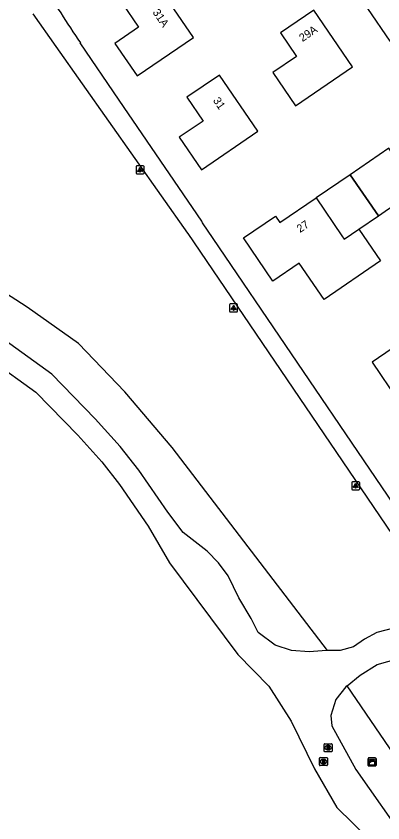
# Model space of a CAD drawing. Extents: x 155275 to 156263, y 382654 to 383635.
# Drawn here: x 155420.9 to 155466.7, y 383140.8 to 383241.6 of the extents above; entities that cross this region are included whole.
import ezdxf

# ---------------------------------------------------------------- set-up
doc = ezdxf.new("R2010")
doc.units = 0
for name, color, linetype in [('IMGEO_Groenvoorziening', 7, 'Continuous'), ('IMGEO_Kast', 7, 'Continuous'), ('IMGEO_Lichtpunt', 7, 'Continuous'), ('IMGEO_Pand', 7, 'Continuous'), ('IMGEO_Pand_nummerreeks', 7, 'Continuous'), ('IMGEO_Pand_overbouw', 7, 'Continuous'), ('IMGEO_Rioolput', 7, 'Continuous'), ('IMGEO_Voetpad_halfverhard', 7, 'Continuous'), ('IMGEO_Voetpad_open', 7, 'Continuous')]:
    doc.layers.add(name, color=color, linetype=linetype)

msp = doc.modelspace()

# ---------------------------------------------------------------- linework, layer by layer
at = {"layer": 'IMGEO_Groenvoorziening'}
for points in [[(155459.78, 383162.34), (155440.37, 383187.68), (155434.48, 383194.63), (155428.68, 383200.68), (155422.29, 383205.23), (155418.85, 383207.42), (155413.45, 383209.36), (155409.53, 383210.67), (155406.49, 383211.64), (155401.05, 383212.16), (155397.68, 383212.16), (155393.94, 383212.01), (155388.96, 383210.31), (155372.51, 383201.68)], [(155532.26, 383055.3), (155462.23, 383157.92)]]:
    msp.add_lwpolyline(points, dxfattribs=at)
at = {"layer": 'IMGEO_Kast'}
for p, q in [((155464.9, 383148.91), (155465.74, 383148.91)), ((155465.74, 383148.91), (155464.9, 383148.91)), ((155464.83, 383147.98), (155464.83, 383148.82)), ((155464.83, 383148.82), (155464.83, 383147.98)), ((155465.75, 383147.91), (155464.91, 383147.91)), ((155464.91, 383147.91), (155465.75, 383147.91)), ((155465.83, 383148.83), (155465.83, 383147.99)), ((155465.83, 383147.99), (155465.83, 383148.83))]:
    msp.add_line(p, q, dxfattribs=at)
for points in [[(155465.02, 383148.7), (155465.62, 383148.7), (155465.62, 383148.61), (155465.02, 383148.61), (155465.02, 383148.7)], [(155465.02, 383148.52), (155465.62, 383148.52), (155465.62, 383148.03), (155465.02, 383148.03), (155465.02, 383148.52)]]:
    msp.add_lwpolyline(points, dxfattribs=at)
msp.add_circle((155465.11, 383148.37), 0.0377, dxfattribs=at)
for centre, start, end in [((155464.91, 383148.83), 92.4484, 184.2845), ((155464.91, 383148.83), 92.4484, 184.2845), ((155465.75, 383148.83), 2.4484, 94.2845), ((155465.75, 383148.83), 2.4484, 94.2845), ((155464.91, 383147.99), 182.4484, 274.2845), ((155464.91, 383147.99), 182.4484, 274.2845), ((155465.75, 383147.99), 272.4484, 4.2845), ((155465.75, 383147.99), 272.4484, 4.2845)]:
    msp.add_arc(centre, 0.0779, start, end, dxfattribs=at)
at = {"layer": 'IMGEO_Lichtpunt'}
for p, q in [((155435.88, 383222.77), (155435.88, 383221.96)), ((155435.88, 383222.77), (155435.88, 383221.96)), ((155436.78, 383222.86), (155435.97, 383222.86)), ((155436.78, 383222.86), (155435.97, 383222.86)), ((155436.87, 383221.96), (155436.87, 383222.77)), ((155436.87, 383221.96), (155436.87, 383222.77)), ((155435.97, 383221.86), (155436.78, 383221.86)), ((155435.97, 383221.86), (155436.78, 383221.86)), ((155447.55, 383205.53), (155447.55, 383204.72)), ((155447.55, 383205.53), (155447.55, 383204.72)), ((155448.45, 383205.62), (155447.64, 383205.62)), ((155448.45, 383205.62), (155447.64, 383205.62)), ((155448.54, 383204.72), (155448.54, 383205.53)), ((155448.54, 383204.72), (155448.54, 383205.53)), ((155447.64, 383204.62), (155448.45, 383204.62)), ((155447.64, 383204.62), (155448.45, 383204.62)), ((155462.79, 383183.3), (155462.79, 383182.5)), ((155462.79, 383183.3), (155462.79, 383182.5)), ((155463.69, 383183.4), (155462.89, 383183.4)), ((155463.69, 383183.4), (155462.89, 383183.4)), ((155463.79, 383182.5), (155463.79, 383183.3)), ((155463.79, 383182.5), (155463.79, 383183.3)), ((155462.89, 383182.4), (155463.69, 383182.4)), ((155462.89, 383182.4), (155463.69, 383182.4))]:
    msp.add_line(p, q, dxfattribs=at)
for points in [[(155436.25, 383222.43), (155436.29, 383222.4), (155436.1, 383222.14), (155436.06, 383222.17), (155436.25, 383222.43)], [(155436.35, 383222.38), (155436.4, 383222.38), (155436.4, 383222.06), (155436.35, 383222.06), (155436.35, 383222.38)], [(155436.46, 383222.4), (155436.5, 383222.43), (155436.69, 383222.17), (155436.65, 383222.14), (155436.46, 383222.4)], [(155447.92, 383205.19), (155447.96, 383205.16), (155447.77, 383204.9), (155447.73, 383204.93), (155447.92, 383205.19)], [(155448.02, 383205.14), (155448.07, 383205.14), (155448.07, 383204.82), (155448.02, 383204.82), (155448.02, 383205.14)], [(155448.13, 383205.16), (155448.17, 383205.19), (155448.36, 383204.93), (155448.32, 383204.9), (155448.13, 383205.16)], [(155463.17, 383182.97), (155463.21, 383182.94), (155463.02, 383182.68), (155462.98, 383182.7), (155463.17, 383182.97)], [(155463.27, 383182.92), (155463.32, 383182.92), (155463.32, 383182.6), (155463.27, 383182.6), (155463.27, 383182.92)], [(155463.38, 383182.94), (155463.42, 383182.97), (155463.6, 383182.7), (155463.57, 383182.68), (155463.38, 383182.94)]]:
    msp.add_lwpolyline(points, dxfattribs=at)
for centre in [(155436.38, 383222.56), (155448.05, 383205.32), (155463.29, 383183.1)]:
    msp.add_circle(centre, 0.0994, dxfattribs=at)
for centre, start, end in [((155435.97, 383222.77), 90, 180), ((155435.97, 383222.77), 90, 180), ((155436.78, 383222.77), 0, 90), ((155436.78, 383222.77), 0, 90), ((155435.97, 383221.96), 180, 270), ((155435.97, 383221.96), 180, 270), ((155436.78, 383221.96), 270, 0), ((155436.78, 383221.96), 270, 360), ((155447.64, 383205.53), 90, 180), ((155447.64, 383205.53), 90, 180), ((155448.45, 383205.53), 0, 90), ((155448.45, 383205.53), 0, 90), ((155447.64, 383204.72), 180, 270), ((155447.64, 383204.72), 180, 270), ((155448.45, 383204.72), 270, 0), ((155448.45, 383204.72), 270, 360), ((155462.89, 383183.3), 90, 180), ((155462.89, 383183.3), 90, 180), ((155463.69, 383183.3), 0, 90), ((155463.69, 383183.3), 0, 90), ((155462.89, 383182.5), 180, 270), ((155462.89, 383182.5), 180, 270), ((155463.69, 383182.5), 270, 0), ((155463.69, 383182.5), 270, 360)]:
    msp.add_arc(centre, 0.0946, start, end, dxfattribs=at)
at = {"layer": 'IMGEO_Pand'}
for points in [[(155469.81, 383250.28), (155465.72, 383247.49), (155467.74, 383244.52), (155464.78, 383242.51), (155467.56, 383238.46), (155474.6, 383243.27), (155469.81, 383250.28)], [(155438.24, 383245.97), (155434.16, 383243.2), (155436.2, 383240.2), (155433.24, 383238.16), (155436.02, 383234.12), (155443.05, 383238.92), (155438.24, 383245.97)], [(155458.08, 383242.32), (155453.92, 383239.49), (155455.92, 383236.53), (155452.95, 383234.51), (155455.79, 383230.35), (155462.91, 383235.22), (155458.08, 383242.32)], [(155446.28, 383234.21), (155442.22, 383231.44), (155444.25, 383228.45), (155441.27, 383226.44), (155444.04, 383222.38), (155451.08, 383227.19), (155446.28, 383234.21)], [(155453.28, 383216.6), (155453.84, 383215.78), (155458.35, 383218.86), (155461.58, 383214.13), (155461.87, 383213.71), (155463.7, 383214.96), (155466.4, 383211.02), (155459.35, 383206.19), (155456.25, 383210.73), (155452.94, 383208.47), (155449.27, 383213.87), (155453.28, 383216.6)], [(155476.21, 383211.82), (155473.43, 383209.92), (155476.24, 383205.79), (155465.34, 383198.36), (155468.55, 383193.62), (155471.85, 383195.86)]]:
    msp.add_lwpolyline(points, dxfattribs=at)
at = {"layer": 'IMGEO_Pand_overbouw'}
for points in [[(155462.6, 383221.76), (155466.12, 383216.61), (155466.97, 383217.19), (155470.96, 383219.9), (155470.82, 383220.1), (155470.67, 383220.31), (155467.43, 383225.06)], [(155462.6, 383221.76), (155458.35, 383218.86), (155461.58, 383214.13), (155461.87, 383213.71), (155463.7, 383214.96), (155466.12, 383216.61)]]:
    msp.add_lwpolyline(points, close=True, dxfattribs=at)
at = {"layer": 'IMGEO_Rioolput'}
for p, q in [((155459.34, 383149.76), (155459.34, 383150.61)), ((155459.42, 383150.69), (155460.27, 383150.69)), ((155459.83, 383150.47), (155459.86, 383150.47)), ((155459.85, 383149.91), (155459.83, 383149.91)), ((155460.34, 383150.61), (155460.34, 383149.76)), ((155458.84, 383148.96), (155459.69, 383148.96)), ((155460.27, 383149.69), (155459.42, 383149.69)), ((155458.76, 383148.04), (155458.76, 383148.89)), ((155459.69, 383147.96), (155458.84, 383147.96)), ((155459.25, 383148.74), (155459.28, 383148.74)), ((155459.27, 383148.18), (155459.25, 383148.18)), ((155459.77, 383148.89), (155459.77, 383148.04))]:
    msp.add_line(p, q, dxfattribs=at)
for points in [[(155459.34, 383149.76), (155459.34, 383150.61)], [(155459.42, 383150.69), (155460.27, 383150.69)], [(155459.93, 383150.38), (155459.68, 383150.39), (155459.68, 383149.99)], [(155459.68, 383149.99), (155459.8, 383149.99), (155459.8, 383150.15), (155459.82, 383150.15)], [(155459.86, 383150.31), (155459.8, 383150.31), (155459.8, 383150.22)], [(155459.8, 383150.22), (155459.86, 383150.22)], [(155459.86, 383150.12), (155459.93, 383149.99), (155460.07, 383149.99), (155460.01, 383150.11)], [(155460.34, 383150.61), (155460.34, 383149.76)], [(155458.84, 383148.96), (155459.69, 383148.96)], [(155460.27, 383149.69), (155459.42, 383149.69)], [(155458.76, 383148.04), (155458.76, 383148.89)], [(155459.69, 383147.96), (155458.84, 383147.96)], [(155459.35, 383148.66), (155459.1, 383148.66), (155459.1, 383148.26)], [(155459.1, 383148.26), (155459.23, 383148.26), (155459.23, 383148.42), (155459.24, 383148.42)], [(155459.28, 383148.58), (155459.23, 383148.58), (155459.23, 383148.5)], [(155459.23, 383148.5), (155459.28, 383148.5)], [(155459.28, 383148.39), (155459.35, 383148.26), (155459.49, 383148.26), (155459.43, 383148.39)], [(155459.77, 383148.89), (155459.77, 383148.04)]]:
    msp.add_lwpolyline(points, dxfattribs=at)
for centre, radius, start, end in [((155459.42, 383150.61), 0.0765, 91.552, 178.448), ((155459.42, 383150.61), 0.0765, 91.552, 178.448), ((155459.81, 383150.1), 0.0533, 26.0293, 88.6989), ((155459.86, 383150.21), 0.0964, 77.0061, 93.1865), ((155459.84, 383150.41), 0.19, 274.7715, 282.9687), ((155459.88, 383150.27), 0.0378, 276.6634, 79.6772), ((155459.93, 383150.28), 0.109, 350.3612, 89.416), ((155459.93, 383150.27), 0.112, 277.5842, 350.9817), ((155459.91, 383150.06), 0.108, 29.5134, 73.7905), ((155460.27, 383150.61), 0.0765, 1.552, 88.448), ((155460.27, 383150.61), 0.0765, 1.552, 88.448), ((155458.84, 383148.89), 0.0765, 91.552, 178.448), ((155458.84, 383148.89), 0.0765, 91.552, 178.448), ((155459.42, 383149.76), 0.0765, 181.552, 268.448), ((155459.42, 383149.76), 0.0765, 181.552, 268.448), ((155459.69, 383148.89), 0.0765, 1.552, 88.448), ((155459.69, 383148.89), 0.0765, 1.552, 88.448), ((155460.27, 383149.76), 0.0765, 271.552, 358.448), ((155460.27, 383149.76), 0.0765, 271.552, 358.448), ((155458.84, 383148.04), 0.0765, 181.552, 268.448), ((155458.84, 383148.04), 0.0765, 181.552, 268.448), ((155459.23, 383148.37), 0.0533, 26.0293, 88.6989), ((155459.28, 383148.48), 0.0964, 77.0061, 93.1865), ((155459.26, 383148.69), 0.19, 274.7715, 282.9687), ((155459.3, 383148.54), 0.0378, 276.6634, 79.6772), ((155459.35, 383148.55), 0.109, 350.3612, 89.416), ((155459.35, 383148.55), 0.112, 277.5842, 350.9817), ((155459.33, 383148.33), 0.108, 29.5134, 73.7905), ((155459.69, 383148.04), 0.0765, 271.552, 358.448), ((155459.69, 383148.04), 0.0765, 271.552, 358.448)]:
    msp.add_arc(centre, radius, start, end, dxfattribs=at)
for centre, major_axis, ratio, start_param, end_param in [((155459.83, 383150.19), (-0.387, 0.002), 0.722429, 4.712389, 7.853982), ((155459.85, 383150.19), (-0.39, 0.002), 0.717154, 1.570796, 4.712389), ((155459.25, 383148.46), (-0.387, 0.002), 0.722429, 4.712389, 7.853982), ((155459.28, 383148.46), (-0.39, 0.002), 0.717154, 1.570796, 4.712389)]:
    msp.add_ellipse(centre, major_axis=major_axis, ratio=ratio, start_param=start_param, end_param=end_param, dxfattribs=at)
at = {"layer": 'IMGEO_Voetpad_halfverhard'}
for points in [[(155459.78, 383162.34), (155459.65, 383162.34), (155457.48, 383162.15), (155455.3, 383162.33), (155453.23, 383163.01), (155451.1, 383164.59), (155450.26, 383166.32), (155448.69, 383168.92), (155447.36, 383171.65), (155446.17, 383173.3), (155444.76, 383174.76), (155441.74, 383177.07), (155439.84, 383179.6), (155436.24, 383184.86), (155433.9, 383187.83), (155430.78, 383191.26), (155425.35, 383196.87), (155419.37, 383201.18)], [(155417.81, 383198.61), (155423.37, 383194.6), (155428.59, 383189.21), (155431.61, 383185.89), (155433.82, 383183.08), (155437.4, 383177.85), (155440.05, 383173.3), (155448.58, 383161.82), (155452.44, 383157.87), (155455.23, 383153.49), (155458.16, 383147.57)], [(155474.79, 383166.6), (155474.68, 383166.56), (155468.34, 383165.21), (155465.92, 383164.58), (155464.41, 383163.77), (155463.01, 383162.79), (155461.36, 383162.34), (155459.78, 383162.34)], [(155462.23, 383157.92), (155463.85, 383159.26), (155465.99, 383160.57), (155468.62, 383161.33), (155472.81, 383162.13), (155477.83, 383162.13)], [(155462.23, 383157.92), (155462.08, 383157.79), (155460.8, 383156.2), (155460.2, 383154.22), (155460.31, 383152.94), (155463.29, 383147.49), (155476.06, 383129.31), (155480.08, 383123.25), (155485.32, 383114.55), (155492.39, 383101.86), (155501.64, 383091.21)], [(155458.16, 383147.57), (155460.95, 383142.74), (155464.94, 383138.83)]]:
    msp.add_lwpolyline(points, dxfattribs=at)
at = {"layer": 'IMGEO_Voetpad_open'}
for points in [[(155423.01, 383241.86), (155425.86, 383237.78), (155442.28, 383214.46), (155442.32, 383214.42), (155474.79, 383166.6)], [(155474.85, 383170.58), (155445.52, 383213.79), (155444.19, 383215.77), (155444.08, 383215.94), (155433.77, 383231.09), (155428.92, 383238.24)]]:
    msp.add_lwpolyline(points, dxfattribs=at)
msp.add_arc((155528.81, 383306.73), 121.11, 210.2146, 214.4373, dxfattribs=at)

# ---------------------------------------------------------------- texts
at = {"layer": 'IMGEO_Pand_nummerreeks'}
for s, rotation, p in [('31A', 304.3028, (155437.89, 383242.05)), ('29A', 34.2113, (155456.65, 383238.32)), ('31', 304.2856, (155445.43, 383231.03)), ('27', 34.3431, (155456.35, 383214.47))]:
    msp.add_text(s, height=1, rotation=rotation, dxfattribs=at).set_placement(p)

doc.saveas('drawing.dxf')
